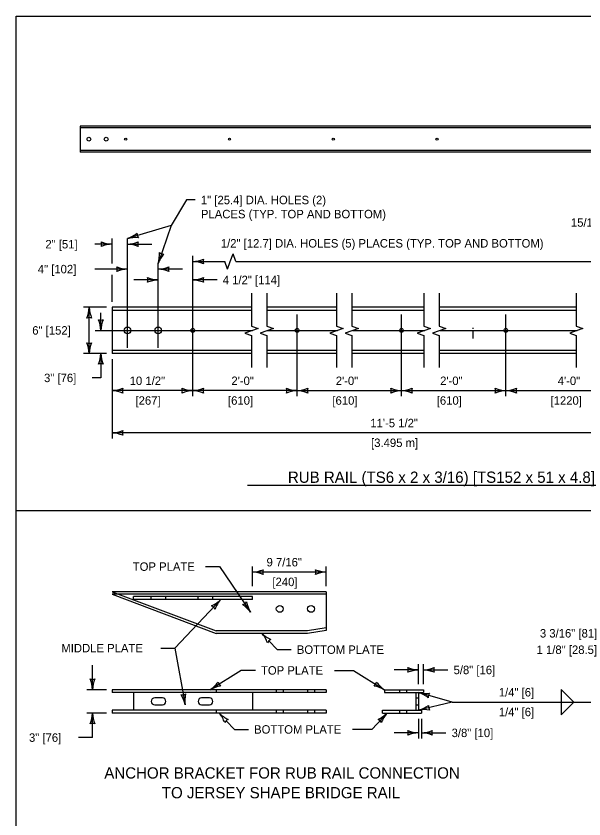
# Model space of a CAD drawing. Extents: x 49991.4 to 50021, y 49987.6 to 50011.4.
# Drawn here: x 49999.38 to 50003.42, y 49993.3 to 49999 of the extents above; entities that cross this region are included whole.
import ezdxf

# ---------------------------------------------------------------- set-up
doc = ezdxf.new("R2010")
doc.units = 0
for name, color, linetype in [('Level 1', 7, 'Continuous'), ('Level 2', 7, 'Continuous'), ('Level 3', 7, 'Continuous'), ('Level 4', 7, 'Continuous'), ('Level 5', 7, 'Continuous'), ('Level 6', 7, 'Continuous')]:
    doc.layers.add(name, color=color, linetype=linetype)

msp = doc.modelspace()

# ---------------------------------------------------------------- linework, layer by layer
at = {"layer": 'Level 1'}
for p, q in [((49999.8398, 49998.2173), (49999.8398, 49998.0329)), ((50004.0368, 49998.2173), (49999.8398, 49998.2173)), ((50004.066, 49998.0329), (49999.8398, 49998.0329)), ((50000.066, 49996.9313), (50000.066, 49996.6038)), ((50001.0562, 49996.9313), (50000.066, 49996.9313)), ((50001.6604, 49996.9313), (50001.1648, 49996.9313)), ((50002.2811, 49996.9313), (50001.769, 49996.9313)), ((50003.3652, 49996.9313), (50002.3897, 49996.9313)), ((50001.0562, 49996.6038), (50000.066, 49996.6038)), ((50001.6604, 49996.6038), (50001.1648, 49996.6038)), ((50002.2811, 49996.6038), (50001.769, 49996.6038)), ((50003.3652, 49996.6038), (50002.3897, 49996.6038)), ((50005.9232, 49995.4868), (49999.3835, 49995.4868)), ((50001.5875, 49994.9119), (50000.0667, 49994.9119)), ((50000.0667, 49994.9119), (50000.8062, 49994.6341)), ((50000.0667, 49994.8945), (50000.8062, 49994.6167)), ((50000.1129, 49994.8945), (50000.0667, 49994.8945)), ((50001.5875, 49994.9119), (50001.5875, 49994.6375)), ((50001.4555, 49994.6341), (50000.8062, 49994.6341)), ((50001.5875, 49994.6549), (50001.4555, 49994.6341)), ((50001.5875, 49994.6375), (50001.4555, 49994.6167)), ((50001.4555, 49994.6167), (50000.8062, 49994.6167)), ((50001.5875, 49994.2167), (50000.0667, 49994.2167)), ((50000.0667, 49994.2167), (50000.0667, 49994.1959)), ((50001.5875, 49994.1959), (50000.0667, 49994.1959)), ((50000.2194, 49994.1959), (50000.2194, 49994.0709)), ((50000.8062, 49994.2167), (50000.8062, 49994.1959)), ((50001.0632, 49994.1959), (50001.0632, 49994.0709)), ((50001.5875, 49994.2167), (50001.5875, 49994.1959)), ((50002.0015, 49994.2167), (50002.2793, 49994.2167)), ((50002.0015, 49994.2167), (50002.0015, 49994.1959)), ((50002.0015, 49994.1959), (50002.2793, 49994.1959)), ((50002.2238, 49994.1959), (50002.2238, 49994.0709)), ((50002.2446, 49994.1959), (50002.2446, 49994.0709)), ((50002.2793, 49994.2167), (50002.2793, 49994.1959)), ((50000.4243, 49994.1577), (50000.3687, 49994.1577)), ((50000.6778, 49994.1334), (50000.6778, 49994.1334)), ((50000.7576, 49994.1577), (50000.7021, 49994.1577)), ((50000.7819, 49994.1334), (50000.7819, 49994.1334)), ((50001.5875, 49994.0709), (50000.0667, 49994.0709)), ((50000.0667, 49994.0709), (50000.0667, 49994.0501)), ((50000.3687, 49994.1091), (50000.4243, 49994.1091)), ((50000.7021, 49994.1091), (50000.7576, 49994.1091)), ((50000.8062, 49994.0709), (50000.8062, 49994.0501)), ((50001.5875, 49994.0709), (50001.5875, 49994.0501)), ((50001.9875, 49994.0709), (50002.2655, 49994.0709)), ((50001.9875, 49994.0501), (50001.9875, 49994.0709)), ((50002.2655, 49994.0709), (50002.2655, 49994.0501)), ((50001.5875, 49994.0501), (50000.0667, 49994.0501)), ((50001.9875, 49994.0501), (50002.2655, 49994.0501))]:
    msp.add_line(p, q, dxfattribs=at)
msp.add_lwpolyline([(49999.3835, 49998.9992), (50016.7501, 49998.9992), (50016.7501, 49987.7988), (49999.3835, 49987.7988)], close=True, dxfattribs=at)
for centre, radius in [((49999.9013, 49998.1251), 0.0134), ((50000.0243, 49998.1251), 0.0134), ((50000.1626, 49998.1251), 0.00768), ((50000.9002, 49998.1251), 0.00768), ((50001.6379, 49998.1251), 0.00768), ((50002.3755, 49998.1251), 0.00768), ((50000.1752, 49996.7673), 0.0239), ((50000.3935, 49996.7673), 0.0239), ((50000.6391, 49996.7673), 0.0136), ((50001.3808, 49996.7673), 0.0136), ((50002.1225, 49996.7673), 0.0136), ((50002.8642, 49996.7673), 0.0136), ((50001.2576, 49994.7903), 0.0243), ((50001.4799, 49994.7903), 0.0243)]:
    msp.add_circle(centre, radius, dxfattribs=at)
for centre, start, end in [((50000.3687, 49994.1334), 90, 270), ((50000.4243, 49994.1334), 270, 90), ((50000.7021, 49994.1334), 90, 270), ((50000.7576, 49994.1334), 270, 90)]:
    msp.add_arc(centre, 0.0243, start, end, dxfattribs=at)
at = {"layer": 'Level 2'}
msp.add_line((50001.0295, 49995.6698), (50004.4578, 49995.6698), dxfattribs=at)
at = {"layer": 'Level 3'}
for p, q in [((50000.6574, 49997.6933), (50000.595, 49997.6933)), ((50000.4851, 49997.5134), (50000.1752, 49997.4194)), ((50000.066, 49997.3794), (49999.943, 49997.3794)), ((50000.066, 49997.2426), (50000.066, 49997.4194)), ((50000.1752, 49997.3794), (50000.3486, 49997.3794)), ((50000.9062, 49997.2571), (50000.9256, 49997.3119)), ((50000.9451, 49997.2571), (50000.9256, 49997.3119)), ((50000.6391, 49997.2571), (50000.8674, 49997.2571)), ((50000.8868, 49997.2023), (50000.8674, 49997.2571)), ((50000.8868, 49997.2023), (50000.9062, 49997.2571)), ((50000.9451, 49997.2571), (50003.794, 49997.2571)), ((50000.1752, 49997.2026), (49999.943, 49997.2026)), ((50000.567, 49997.2026), (50000.3935, 49997.2026)), ((50000.066, 49996.9713), (50000.066, 49997.1626)), ((50000.3935, 49997.1257), (50000.2201, 49997.1257)), ((50000.8126, 49997.1257), (50000.6391, 49997.1257)), ((50000.026, 49996.9313), (49999.8636, 49996.9313)), ((49999.9036, 49996.6038), (49999.9036, 49996.9313)), ((49999.986, 49996.7673), (49999.986, 49996.8924)), ((50000.026, 49996.6038), (49999.8636, 49996.6038)), ((49999.986, 49996.6038), (49999.986, 49996.4303)), ((50000.066, 49996.5638), (50000.0661, 49995.9997)), ((49999.986, 49996.4303), (49999.9236, 49996.4303)), ((50000.6391, 49996.3397), (50000.0661, 49996.3397)), ((50001.3808, 49996.3397), (50000.6391, 49996.3397)), ((50001.3808, 49996.3397), (50002.1225, 49996.3397)), ((50002.1225, 49996.3397), (50002.8642, 49996.3397)), ((50002.8642, 49996.3397), (50003.794, 49996.3397)), ((50004.176, 49996.0397), (50000.0661, 49996.0397)), ((50001.0632, 49994.9519), (50001.0632, 49995.0919)), ((50001.5875, 49994.9519), (50001.5875, 49995.0919)), ((50001.5875, 49995.0519), (50001.0632, 49995.0519)), ((50000.5122, 49994.5116), (50000.586, 49994.1087)), ((49999.9267, 49994.2167), (49999.9267, 49994.3902)), ((50002.2446, 49994.3567), (50002.0712, 49994.3567)), ((50002.2446, 49994.2567), (50002.2446, 49994.3967)), ((50002.2793, 49994.2567), (50002.2793, 49994.3967)), ((50002.2793, 49994.3567), (50002.4528, 49994.3567)), ((50000.0267, 49994.2167), (49999.8867, 49994.2167)), ((50002.4824, 49994.1283), (50002.2446, 49994.1959)), ((50002.4824, 49994.1283), (50002.2446, 49994.0709)), ((50000.0267, 49994.0501), (49999.8867, 49994.0501)), ((49999.9267, 49993.8766), (49999.9267, 49994.0501)), ((50002.2446, 49994.0101), (50002.2446, 49993.8701)), ((50002.2655, 49994.0101), (50002.2655, 49993.8701)), ((50002.2446, 49993.9101), (50002.0712, 49993.9101)), ((50002.2655, 49993.9101), (50002.4389, 49993.9101)), ((49999.9267, 49993.8766), (49999.8267, 49993.8766))]:
    msp.add_line(p, q, dxfattribs=at)
for points in [[(50000.595, 49997.6933), (50000.4851, 49997.5134), (50000.3935, 49997.2426)], [(50000.7303, 49995.0906), (50000.8303, 49995.0906), (50001.0505, 49994.7672)], [(50000.4122, 49994.5116), (50000.5122, 49994.5116), (50000.8382, 49994.8563)], [(50001.181, 49994.5631), (50001.239, 49994.5011), (50001.339, 49994.5011)], [(50001.0842, 49994.3535), (50000.9842, 49994.3535), (50000.7637, 49994.2167)], [(50001.6463, 49994.3535), (50001.781, 49994.3535), (50002.0015, 49994.2167)], [(50003.2582, 49994.2174), (50003.2582, 49994.0391), (50003.3473, 49994.1283)], [(50003.2582, 49994.2174), (50003.3473, 49994.1283)], [(50002.4824, 49994.1283), (50003.5194, 49994.1283)], [(50002.0201, 49994.0501), (50001.912, 49993.9344), (50001.7746, 49993.9344)], [(50000.8772, 49993.9964), (50000.9352, 49993.9344), (50001.0352, 49993.9344)]]:
    msp.add_lwpolyline(points, dxfattribs=at)
for centre, radius, start, end in [((50000.0966, 49997.6387), 0.233, 289.7148, 308.9646), ((50000.231, 49997.2042), 0.2223, 84.3435, 104.527), ((50000.2979, 49997.4566), 0.0548, 179.0263, 214.7486), ((50000.0752, 49997.6015), 0.2223, 247.456, 267.6395), ((49999.9378, 49997.3794), 0.0548, 342.1388, 17.8612), ((50000.0775, 49997.1467), 0.233, 92.8273, 112.0772), ((50000.1637, 49997.6121), 0.233, 272.8273, 292.0772), ((50000.1661, 49997.1573), 0.2223, 67.456, 87.6395), ((50000.3034, 49997.3794), 0.0548, 162.1388, 197.8612), ((50000.1694, 49997.3062), 0.233, 344.1533, 3.4031), ((50000.601, 49997.1628), 0.2223, 138.782, 158.9655), ((50000.4346, 49997.3641), 0.0548, 233.4648, 269.1872), ((50000.6276, 49997.4898), 0.233, 272.8278, 292.0777), ((50000.63, 49997.0349), 0.2223, 67.4565, 87.64), ((50000.7674, 49997.2571), 0.0548, 162.1393, 197.8617), ((50000.1844, 49997.4247), 0.2223, 247.456, 267.6395), ((50000.047, 49997.2026), 0.0548, 342.1388, 17.8612), ((50000.1867, 49996.9699), 0.233, 92.8273, 112.0772), ((50000.3844, 49997.4247), 0.2223, 272.3605, 292.544), ((50000.382, 49996.9699), 0.233, 67.9228, 87.1727), ((50000.5217, 49997.2026), 0.0548, 162.1388, 197.8612), ((50000.4027, 49997.3479), 0.2223, 247.456, 267.6395), ((50000.2653, 49997.1257), 0.0548, 342.1388, 17.8612), ((50000.63, 49997.3479), 0.2223, 272.3605, 292.544), ((50000.7674, 49997.1257), 0.0548, 162.1388, 197.8612), ((50000.405, 49996.893), 0.233, 92.8273, 112.0772), ((50000.6277, 49996.893), 0.233, 67.9228, 87.1727), ((49999.6815, 49996.9404), 0.2223, 337.456, 357.6395), ((50000.1364, 49996.9428), 0.233, 182.8273, 202.0772), ((49999.9036, 49996.8031), 0.0548, 72.1388, 107.8612), ((49999.986, 49996.8955), 0.0548, 252.1388, 287.8612), ((49999.7533, 49996.7558), 0.233, 2.8273, 22.0772), ((50000.2082, 49996.7582), 0.2223, 157.456, 177.6395), ((49999.9036, 49996.732), 0.0548, 252.1388, 287.8612), ((49999.6709, 49996.5923), 0.233, 2.8273, 22.0772), ((50000.1258, 49996.5946), 0.2223, 157.456, 177.6395), ((49999.7533, 49996.6153), 0.233, 337.9228, 357.1727), ((50000.2082, 49996.6129), 0.2223, 182.3605, 202.544), ((49999.986, 49996.4756), 0.0548, 72.1388, 107.8612), ((50000.0569, 49996.5618), 0.2223, 272.3605, 292.544), ((50000.1943, 49996.3397), 0.0548, 162.1388, 197.8612), ((50000.6483, 49996.5618), 0.2223, 247.456, 267.6395), ((50000.5109, 49996.3397), 0.0548, 342.1388, 17.8612), ((50000.6277, 49996.5724), 0.233, 272.8273, 292.0772), ((50000.7674, 49996.3397), 0.0548, 162.1388, 197.8612), ((50001.2526, 49996.3397), 0.0548, 342.1388, 17.8612), ((50001.3923, 49996.5724), 0.233, 247.9228, 267.1727), ((50001.3717, 49996.5618), 0.2223, 272.3605, 292.544), ((50001.5091, 49996.3397), 0.0548, 162.1388, 197.8612), ((50002.1317, 49996.5618), 0.2223, 247.456, 267.6395), ((50001.9943, 49996.3397), 0.0548, 342.1388, 17.8612), ((50002.1134, 49996.5618), 0.2223, 272.3605, 292.544), ((50002.2508, 49996.3397), 0.0548, 162.1388, 197.8612), ((50002.8734, 49996.5618), 0.2223, 247.456, 267.6395), ((50002.736, 49996.3397), 0.0548, 342.1388, 17.8612), ((50002.8527, 49996.5724), 0.233, 272.8273, 292.0772), ((50002.9924, 49996.3397), 0.0548, 162.1388, 197.8612), ((50000.0546, 49996.107), 0.233, 67.9228, 87.1727), ((50000.6506, 49996.107), 0.233, 92.8273, 112.0772), ((50000.63, 49996.1175), 0.2223, 67.456, 87.6395), ((50001.39, 49996.1175), 0.2223, 92.3605, 112.544), ((50001.3694, 49996.107), 0.233, 67.9228, 87.1727), ((50002.134, 49996.107), 0.233, 92.8273, 112.0772), ((50002.111, 49996.107), 0.233, 67.9228, 87.1727), ((50002.8757, 49996.107), 0.233, 92.8273, 112.0772), ((50002.8551, 49996.1175), 0.2223, 67.456, 87.6395), ((50000.057, 49996.2618), 0.2223, 272.3605, 292.544), ((50000.1944, 49996.0397), 0.0548, 162.1388, 197.8612), ((50000.0546, 49995.807), 0.233, 67.9228, 87.1727), ((50001.054, 49995.274), 0.2223, 272.3605, 292.544), ((50001.0517, 49994.8191), 0.233, 67.9228, 87.1727), ((50001.1914, 49995.0519), 0.0548, 162.1388, 197.8612), ((50001.4593, 49995.0519), 0.0548, 342.1388, 17.8612), ((50001.599, 49995.2846), 0.233, 247.9228, 267.1727), ((50001.5966, 49994.8297), 0.2223, 92.3605, 112.544), ((50000.6831, 49995.0156), 0.2223, 294.0606, 314.2441), ((50000.7501, 49994.7631), 0.0548, 28.7434, 64.4657), ((50001.0152, 49994.7048), 0.233, 139.4319, 158.6817), ((50000.9783, 49994.8732), 0.0548, 286.3802, 322.1025), ((50000.872, 49994.6346), 0.2223, 36.6018, 56.7853), ((50001.2493, 49994.8886), 0.233, 192.1642, 211.414), ((50000.9624, 49994.4717), 0.2223, 20.5277, 40.7112), ((50001.293, 49994.784), 0.233, 225.899, 245.1489), ((50001.2184, 49994.523), 0.0548, 115.2105, 150.9329), ((50002.1164, 49994.3567), 0.0548, 342.1388, 17.8612), ((50002.2561, 49994.5894), 0.233, 247.9228, 267.1727), ((50002.2538, 49994.1346), 0.2223, 92.3605, 112.544), ((50002.2679, 49994.5894), 0.233, 272.8273, 292.0772), ((50002.2702, 49994.1346), 0.2223, 67.456, 87.6395), ((50002.4076, 49994.3567), 0.0548, 162.1388, 197.8612), ((49999.9267, 49994.3449), 0.0548, 252.1388, 287.8612), ((49999.6939, 49994.2052), 0.233, 2.8273, 22.0772), ((50000.1488, 49994.2076), 0.2223, 157.456, 177.6395), ((50000.6388, 49994.4006), 0.2223, 304.1791, 324.3626), ((50000.8766, 49994.0129), 0.233, 99.7415, 118.9913), ((50000.8726, 49994.2843), 0.0548, 193.9575, 229.6798), ((50001.8925, 49994.2843), 0.0548, 310.3202, 346.0425), ((50001.8886, 49994.0129), 0.233, 61.0087, 80.2585), ((50002.1264, 49994.4006), 0.2223, 215.6374, 235.8209), ((50000.5629, 49994.2348), 0.0548, 262.5124, 298.2348), ((50000.3592, 49994.0555), 0.233, 13.2009, 32.4508), ((50000.8061, 49994.1397), 0.2223, 167.8296, 188.0131), ((50002.1751, 49993.9847), 0.2223, 51.58, 71.7635), ((50002.2972, 49994.4229), 0.233, 256.9513, 276.2011), ((50002.3679, 49994.1608), 0.0548, 146.2628, 181.9851), ((50002.1789, 49994.2944), 0.233, 286.3912, 305.6411), ((50002.2878, 49993.8528), 0.2223, 81.0199, 101.2034), ((50002.3693, 49994.101), 0.0548, 175.7027, 211.4251), ((49999.7045, 49994.0592), 0.2223, 337.456, 357.6395), ((50000.1594, 49994.0615), 0.233, 182.8273, 202.0772), ((50000.6585, 49993.905), 0.2223, 20.5277, 40.7112), ((50000.9892, 49994.2174), 0.233, 225.899, 245.1489), ((50000.9146, 49993.9564), 0.0548, 115.2105, 150.9329), ((50001.858, 49994.2174), 0.233, 294.8511, 314.101), ((50001.9326, 49993.9564), 0.0548, 29.0671, 64.7895), ((50002.1887, 49993.905), 0.2223, 139.2888, 159.4723), ((49999.9267, 49993.9218), 0.0548, 72.1388, 107.8612), ((50002.2538, 49994.1322), 0.2223, 247.456, 267.6395), ((50002.1164, 49993.9101), 0.0548, 342.1388, 17.8612), ((50002.2561, 49993.6773), 0.233, 92.8273, 112.0772), ((50002.2563, 49994.1322), 0.2223, 272.3605, 292.544), ((50002.254, 49993.6773), 0.233, 67.9228, 87.1727), ((50002.3937, 49993.9101), 0.0548, 162.1388, 197.8612)]:
    msp.add_arc(centre, radius, start, end, dxfattribs=at)
at = {"layer": 'Level 4'}
for p, q in [((50004.0387, 49998.2052), (49999.8398, 49998.2052)), ((50004.0641, 49998.045), (49999.8398, 49998.045)), ((50001.0562, 49996.9098), (50000.066, 49996.9098)), ((50001.6604, 49996.9098), (50001.1648, 49996.9098)), ((50002.2811, 49996.9098), (50001.769, 49996.9098)), ((50003.3652, 49996.9098), (50002.3897, 49996.9098)), ((50001.0562, 49996.6253), (50000.066, 49996.6253)), ((50001.6604, 49996.6253), (50001.1648, 49996.6253)), ((50002.2811, 49996.6253), (50001.769, 49996.6253)), ((50003.3652, 49996.6253), (50002.3897, 49996.6253)), ((50001.5875, 49994.8945), (50000.1129, 49994.8945)), ((50000.2194, 49994.8563), (50000.2194, 49994.8771)), ((50001.0632, 49994.8771), (50000.2194, 49994.8771)), ((50000.3444, 49994.8563), (50000.3444, 49994.8771)), ((50000.4486, 49994.8563), (50000.4486, 49994.8771)), ((50000.6778, 49994.8563), (50000.6778, 49994.8771)), ((50000.7819, 49994.8563), (50000.7819, 49994.8771)), ((50001.0632, 49994.8563), (50001.0632, 49994.8771)), ((50001.0632, 49994.8563), (50000.2194, 49994.8563)), ((50001.2333, 49994.2167), (50001.2333, 49994.1959)), ((50001.2819, 49994.2167), (50001.2819, 49994.1959)), ((50001.4555, 49994.2167), (50001.4555, 49994.1959)), ((50001.5042, 49994.2167), (50001.5042, 49994.1959)), ((50002.1092, 49994.2167), (50002.1092, 49994.1959)), ((50002.1579, 49994.2167), (50002.1579, 49994.1959)), ((50002.2238, 49994.1577), (50002.2446, 49994.1577)), ((50001.2333, 49994.0709), (50001.2333, 49994.0501)), ((50001.2819, 49994.0709), (50001.2819, 49994.0501)), ((50001.4555, 49994.0709), (50001.4555, 49994.0501)), ((50001.5042, 49994.0709), (50001.5042, 49994.0501)), ((50002.1092, 49994.0709), (50002.1092, 49994.0501)), ((50002.1579, 49994.0709), (50002.1579, 49994.0501)), ((50002.2238, 49994.1091), (50002.2446, 49994.1091))]:
    msp.add_line(p, q, dxfattribs=at)
at = {"layer": 'Level 5'}
for p, q in [((50000.1752, 49996.6435), (50000.1752, 49997.4194)), ((50000.6391, 49996.2997), (50000.6391, 49997.2971)), ((50000.3935, 49996.6435), (50000.3935, 49997.2426)), ((50001.3808, 49996.2997), (50001.3808, 49996.881)), ((50002.1225, 49996.2997), (50002.1225, 49996.881)), ((50002.8642, 49996.2997), (50002.8642, 49996.881)), ((49999.946, 49996.7673), (50001.063, 49996.7673)), ((50001.1716, 49996.7673), (50001.6672, 49996.7673)), ((50001.7758, 49996.7673), (50002.2879, 49996.7673)), ((50002.3965, 49996.7673), (50003.372, 49996.7673))]:
    msp.add_line(p, q, dxfattribs=at)
at = {"layer": 'Level 6'}
for p, q in [((50001.0562, 49997.0313), (50001.0562, 49996.7983)), ((50001.1648, 49997.0313), (50001.1648, 49996.7983)), ((50001.6604, 49997.0313), (50001.6604, 49996.7983)), ((50001.769, 49997.0313), (50001.769, 49996.7983)), ((50002.2811, 49997.0313), (50002.2811, 49996.7983)), ((50002.3897, 49997.0313), (50002.3897, 49996.7983)), ((50003.3652, 49997.0313), (50003.3652, 49996.7983)), ((50001.0562, 49996.7983), (50001.1034, 49996.7816)), ((50001.1648, 49996.7983), (50001.212, 49996.7816)), ((50001.6604, 49996.7983), (50001.7076, 49996.7816)), ((50001.769, 49996.7983), (50001.8162, 49996.7816)), ((50002.2811, 49996.7983), (50002.3282, 49996.7816)), ((50002.3897, 49996.7983), (50002.4368, 49996.7816)), ((50003.3652, 49996.7983), (50003.4123, 49996.7816)), ((50001.0562, 49996.7649), (50001.0091, 49996.7482)), ((50001.0091, 49996.7482), (50001.0562, 49996.7314)), ((50001.1034, 49996.7816), (50001.0562, 49996.7649)), ((50001.1648, 49996.7649), (50001.1177, 49996.7482)), ((50001.1177, 49996.7482), (50001.1648, 49996.7314)), ((50001.212, 49996.7816), (50001.1648, 49996.7649)), ((50001.6604, 49996.7649), (50001.6133, 49996.7482)), ((50001.6133, 49996.7482), (50001.6604, 49996.7314)), ((50001.7076, 49996.7816), (50001.6604, 49996.7649)), ((50001.769, 49996.7649), (50001.7219, 49996.7482)), ((50001.7219, 49996.7482), (50001.769, 49996.7314)), ((50001.8162, 49996.7816), (50001.769, 49996.7649)), ((50002.2811, 49996.7649), (50002.234, 49996.7482)), ((50002.234, 49996.7482), (50002.2811, 49996.7314)), ((50002.3282, 49996.7816), (50002.2811, 49996.7649)), ((50002.3897, 49996.7649), (50002.3426, 49996.7482)), ((50002.3426, 49996.7482), (50002.3897, 49996.7314)), ((50002.4368, 49996.7816), (50002.3897, 49996.7649)), ((50003.3652, 49996.7649), (50003.3181, 49996.7482)), ((50003.3181, 49996.7482), (50003.3652, 49996.7314)), ((50003.4123, 49996.7816), (50003.3652, 49996.7649)), ((50001.0562, 49996.7314), (50001.0562, 49996.5038)), ((50001.1648, 49996.7314), (50001.1648, 49996.5038)), ((50001.6604, 49996.7314), (50001.6604, 49996.5038)), ((50001.769, 49996.7314), (50001.769, 49996.5038)), ((50002.2811, 49996.7314), (50002.2811, 49996.5038)), ((50002.3897, 49996.7314), (50002.3897, 49996.5038)), ((50003.3652, 49996.7314), (50003.3652, 49996.5038))]:
    msp.add_line(p, q, dxfattribs=at)

# ---------------------------------------------------------------- texts
at = {"layer": 'Level 2'}
for s, height, p in [('1" [25.4] DIA. HOLES (2) ', 0.06, (50000.6974, 49997.6633)), ('PLACES (TYP. TOP AND BOTTOM)', 0.06, (50000.6974, 49997.5633)), ('2" [51]', 0.06, (49999.5919, 49997.3494)), (' 1/2" [12.7] DIA. HOLES (5) PLACES (TYP. TOP AND BOTTOM)', 0.06, (50000.8165, 49997.3558)), ('4" [102]', 0.06, (49999.538, 49997.1726)), ('4 1/2" [114]', 0.06, (50000.8526, 49997.0957)), ('6" [152]', 0.06, (49999.4987, 49996.7375)), ('¡', 0.08, (50002.6132, 49996.7263)), ('3" [76]', 0.06, (49999.5825, 49996.4003)), ('10 1/2"', 0.06, (50000.191, 49996.3797)), ('2\'-0"', 0.06, (50000.9139, 49996.3797)), ('2\'-0"', 0.06, (50001.6556, 49996.3797)), ('2\'-0"', 0.06, (50002.3973, 49996.3797)), ('4\'-0"', 0.06, (50003.233, 49996.3797)), ('[267]', 0.06, (50000.2324, 49996.2397)), ('[610]', 0.06, (50000.8898, 49996.2397)), ('[610]', 0.06, (50001.6316, 49996.2397)), ('[610]', 0.06, (50002.3733, 49996.2397)), ('[1220]', 0.06, (50003.1819, 49996.2397)), ('11\'-5 1/2"', 0.06, (50001.9013, 49996.0797)), ('[3.495 m]', 0.06, (50001.9065, 49995.9397)), ('RUB RAIL (TS6 x 2 x 3/16) [TS152 x 51 x 4.8]', 0.08, (50001.3155, 49995.6852)), ('3" [76]', 0.06, (49999.4756, 49993.8466)), ('ANCHOR BRACKET FOR RUB RAIL CONNECTION', 0.08, (50000.0108, 49993.5855)), ('TO JERSEY SHAPE BRIDGE RAIL', 0.08, (50000.4195, 49993.4455))]:
    msp.add_text(s, height=height, dxfattribs=at).set_placement(p)
for s, p in [('15/16" [23.8]', (50003.3268, 49997.5034)), ('9 7/16"', (50001.1637, 49995.0919)), ('TOP PLATE', (50000.213, 49995.0606)), ('[240]', (50001.2052, 49994.9519)), ('3 3/16" [81]', (50003.1063, 49994.5871)), ('MIDDLE PLATE', (49999.7054, 49994.4816)), ('BOTTOM PLATE', (50001.379, 49994.4711)), ('1 1/8" [28.5]', (50003.0827, 49994.4703)), ('TOP PLATE', (50001.1242, 49994.3235)), ('5/8" [16]', (50002.4928, 49994.3267)), ('1/4" [6]', (50002.8143, 49994.1683)), ('1/4" [6]', (50002.8143, 49994.0283)), ('BOTTOM PLATE', (50001.0752, 49993.9044)), ('3/8" [10]', (50002.4789, 49993.8801))]:
    msp.add_text(s, height=0.06, rotation=360, dxfattribs=at).set_placement(p)

doc.saveas('drawing.dxf')
